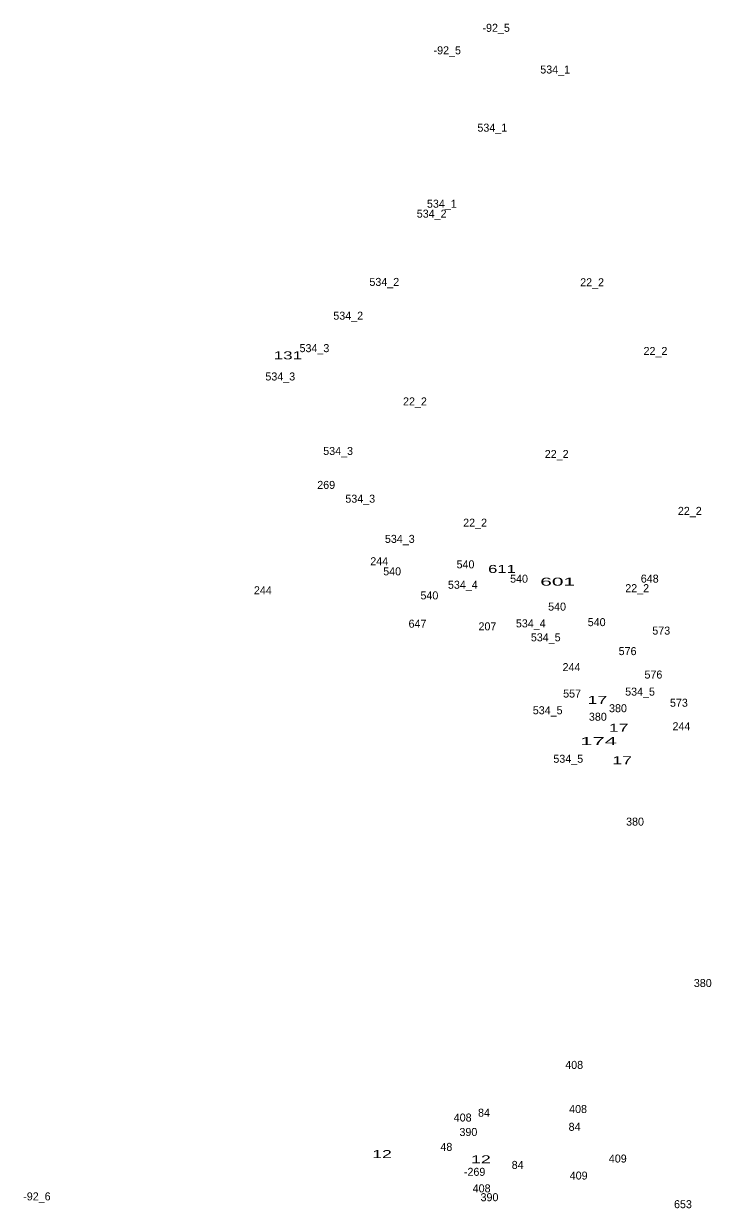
# Model space of a CAD drawing. Extents: x -661742 to -657295, y -1002932 to -996888.
# Drawn here: x -660222 to -659878, y -999837 to -999244 of the extents above; entities that cross this region are included whole.
import ezdxf
from ezdxf.enums import TextEntityAlignment as Align

# ---------------------------------------------------------------- set-up
doc = ezdxf.new("R2010")
doc.units = 0
doc.header["$LTSCALE"] = 1.6
doc.layers.add('24', color=7, linetype='Continuous')

msp = doc.modelspace()

# ---------------------------------------------------------------- texts
at = {"layer": '24'}
for s, p in [('-92_5', (-659985.608, -999248.4)), ('-92_5', (-660010.038, -999259.65)), ('534_1', (-659956.133, -999269.24)), ('534_1', (-659987.543, -999298.33)), ('534_1', (-660012.743, -999336.34)), ('534_2', (-660017.84, -999341.3)), ('534_2', (-660041.49, -999375.43)), ('22_2', (-659937.675, -999375.6)), ('534_2', (-660059.52, -999392.31)), ('534_3', (-660076.39, -999408.54)), ('22_2', (-659906.035, -999409.94)), ('534_3', (-660093.45, -999422.69)), ('22_2', (-660026.175, -999435.16)), ('534_3', (-660064.56, -999459.93)), ('22_2', (-659955.375, -999461.45)), ('269', (-660070.518, -999476.9)), ('534_3', (-660053.51, -999483.79)), ('22_2', (-659888.875, -999489.89)), ('22_2', (-659996.145, -999495.79)), ('534_3', (-660033.74, -999503.88)), ('244', (-660044.026, -999515.06)), ('540', (-660000.935, -999516.61)), ('540', (-660037.575, -999520.1)), ('540', (-659974.185, -999523.79)), ('648', (-659908.897, -999523.75)), ('244', (-660102.156, -999529.57)), ('534_4', (-660002.254, -999526.82)), ('22_2', (-659915.155, -999528.52)), ('540', (-660018.965, -999532.13)), ('540', (-659955.185, -999537.75)), ('647', (-660024.913, -999546.27)), ('207', (-659989.977, -999547.61)), ('534_4', (-659968.324, -999546.12)), ('540', (-659935.405, -999545.51)), ('534_5', (-659960.84, -999553.09)), ('573', (-659903.143, -999549.73)), ('576', (-659919.958, -999559.98)), ('244', (-659947.976, -999568)), ('576', (-659907.068, -999571.71)), ('557', (-659947.693, -999581.2)), ('534_5', (-659913.73, -999580.24)), ('534_5', (-659959.87, -999589.55)), ('380', (-659924.751, -999588.53)), ('573', (-659894.323, -999585.8)), ('380', (-659934.811, -999592.79)), ('244', (-659893.056, -999597.55)), ('534_5', (-659949.6, -999613.8)), ('380', (-659916.241, -999645.22)), ('380', (-659882.401, -999725.9)), ('408', (-659946.635, -999766.83)), ('84', (-659991.691, -999790.73)), ('408', (-659944.705, -999788.89)), ('408', (-660002.335, -999793.15)), ('84', (-659946.441, -999797.79)), ('390', (-659999.487, -999800.38)), ('48', (-660010.491, -999807.82)), ('409', (-659924.861, -999813.65)), ('-269', (-659996.375, -999820.29)), ('84', (-659974.871, -999816.84)), ('409', (-659944.401, -999822.16)), ('-92_6', (-660215.013, -999832.57)), ('408', (-659992.865, -999828.55)), ('390', (-659988.947, -999832.98)), ('653', (-659892.293, -999836.47))]:
    msp.add_text(s, height=4, dxfattribs=at).set_placement(p, align=Align.CENTER)
for s, width, p in [('131', 1.6, (-660089.674, -999412.14)), ('611', 1.55, (-659982.709, -999518.91)), ('601', 1.95, (-659954.879, -999525.27)), ('17', 1.65, (-659935.063, -999584.37)), ('17', 1.65, (-659924.423, -999598.3)), ('174', 2.05, (-659934.448, -999604.99)), ('17', 1.65, (-659922.693, -999614.56)), ('12', 1.65, (-660042.637, -999811.43)), ('12', 1.65, (-659993.217, -999814.04))]:
    msp.add_text(s, height=4, dxfattribs=dict(at, width=width)).set_placement(p, align=Align.CENTER)

doc.saveas('drawing.dxf')
